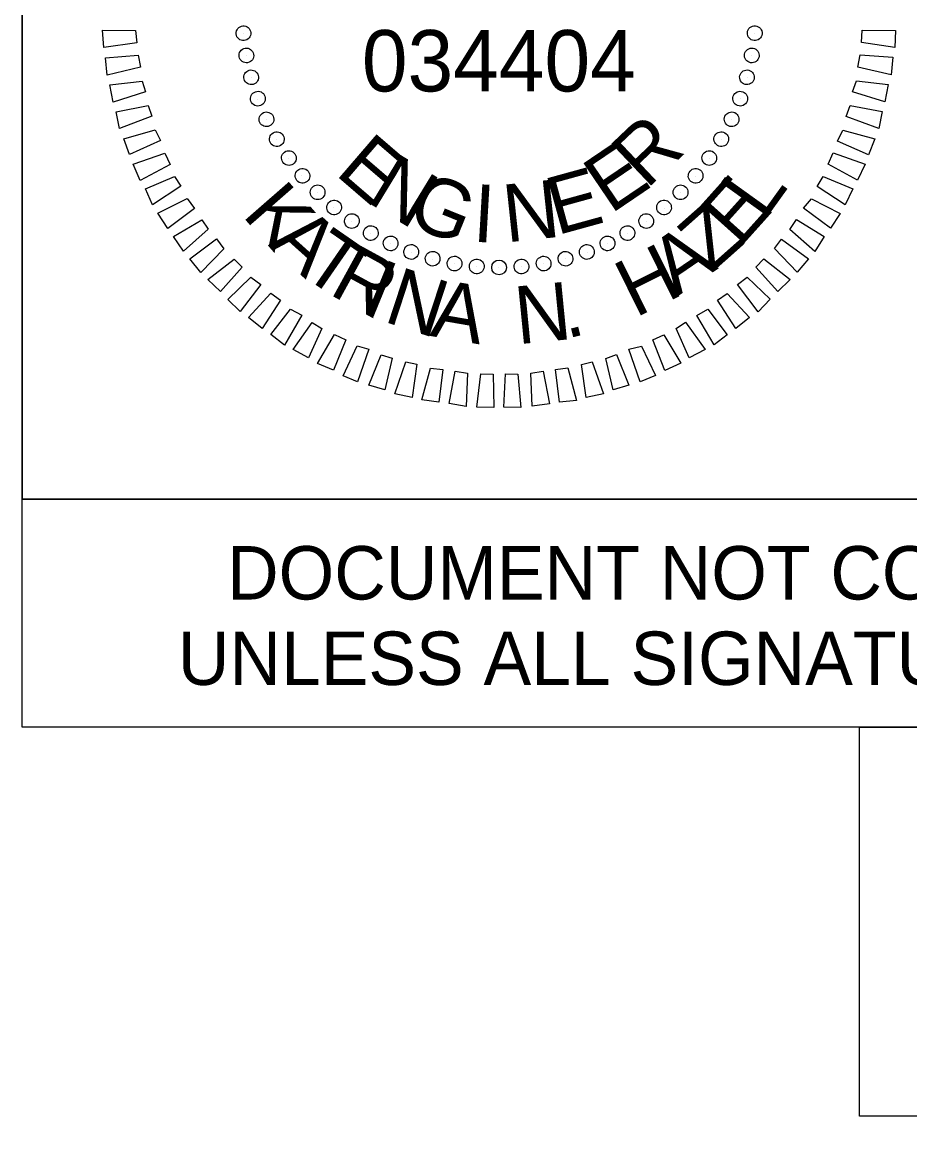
# Model space of a CAD drawing. Extents: x 2320980 to 2456309, y 595047 to 606177.
# Drawn here: x 2456002.1 to 2456020.37, y 597570.06 to 597592.89 of the extents above; entities that cross this region are included whole.
import ezdxf

# ---------------------------------------------------------------- set-up
doc = ezdxf.new("R2010")
doc.units = 0
for name, color, linetype in [('Scratch_Level_0', 7, 'Continuous'), ('Sheet Data Field CELL', 7, 'Continuous'), ('Sheet Plan CELL', 7, 'Continuous'), ('Sheet Sticker Exception Certification CELL', 7, 'Continuous')]:
    doc.layers.add(name, color=color, linetype=linetype)

msp = doc.modelspace()

# ---------------------------------------------------------------- linework, layer by layer
at = {"layer": 'Scratch_Level_0'}
msp.add_lwpolyline([(2456019.333, 597578.364), (2456042.107, 597578.366), (2456042.108, 597570.357), (2456019.334, 597570.354)], close=True, dxfattribs=at)
at = {"layer": 'Sheet Data Field CELL'}
for p, q in [((2456006.644, 597592.658), (2456006.644, 597592.658)), ((2456017.178, 597592.652), (2456017.178, 597592.652)), ((2456006.715, 597592.206), (2456006.715, 597592.206)), ((2456017.112, 597592.198), (2456017.112, 597592.198)), ((2456006.807, 597591.744), (2456006.807, 597591.744)), ((2456017.025, 597591.754), (2456017.025, 597591.754)), ((2456006.942, 597591.304), (2456006.942, 597591.304)), ((2456016.885, 597591.309), (2456016.885, 597591.309)), ((2456007.117, 597590.886), (2456007.117, 597590.886)), ((2456016.703, 597590.884), (2456016.703, 597590.884)), ((2456007.335, 597590.479), (2456007.335, 597590.479)), ((2456016.499, 597590.47), (2456016.499, 597590.47)), ((2456007.584, 597590.083), (2456007.584, 597590.083)), ((2456016.243, 597590.086), (2456016.243, 597590.086)), ((2456007.854, 597589.719), (2456007.854, 597589.719)), ((2456015.965, 597589.713), (2456015.965, 597589.713)), ((2456008.176, 597589.377), (2456008.176, 597589.377)), ((2456015.655, 597589.381), (2456015.655, 597589.381)), ((2456008.508, 597589.067), (2456008.508, 597589.067)), ((2456015.313, 597589.059), (2456015.313, 597589.059)), ((2456008.881, 597588.789), (2456008.881, 597588.789)), ((2456014.949, 597588.789), (2456014.949, 597588.789)), ((2456009.265, 597588.532), (2456009.265, 597588.532)), ((2456014.553, 597588.54), (2456014.553, 597588.54)), ((2456009.679, 597588.329), (2456009.679, 597588.329)), ((2456014.146, 597588.322), (2456014.146, 597588.322)), ((2456010.104, 597588.146), (2456010.104, 597588.146)), ((2456010.549, 597588.007), (2456010.549, 597588.007)), ((2456013.287, 597588.012), (2456013.287, 597588.012)), ((2456013.728, 597588.146), (2456013.728, 597588.146)), ((2456010.993, 597587.92), (2456010.993, 597587.92)), ((2456011.447, 597587.854), (2456011.447, 597587.854)), ((2456011.911, 597587.83), (2456011.911, 597587.83)), ((2456012.374, 597587.849), (2456012.374, 597587.849)), ((2456012.826, 597587.92), (2456012.826, 597587.92))]:
    msp.add_line(p, q, dxfattribs=at)
for points in [[(2456004.456, 597592.461), (2456003.774, 597592.365), (2456003.746, 597592.723), (2456004.431, 597592.714)], [(2456019.388, 597592.722), (2456020.073, 597592.713), (2456020.058, 597592.365), (2456019.372, 597592.469)], [(2456004.529, 597591.957), (2456003.847, 597591.798), (2456003.809, 597592.155), (2456004.482, 597592.209)], [(2456019.344, 597592.216), (2456020.02, 597592.164), (2456019.984, 597591.805), (2456019.296, 597591.962)], [(2456004.632, 597591.453), (2456003.972, 597591.242), (2456003.903, 597591.598), (2456004.565, 597591.673)], [(2456019.27, 597591.677), (2456019.924, 597591.604), (2456019.856, 597591.245), (2456019.189, 597591.454)], [(2456004.767, 597590.95), (2456004.098, 597590.696), (2456004.028, 597591.042), (2456004.69, 597591.17)], [(2456019.142, 597591.169), (2456019.797, 597591.044), (2456019.729, 597590.695), (2456019.061, 597590.947)], [(2456004.945, 597590.447), (2456004.307, 597590.162), (2456004.186, 597590.487), (2456004.835, 597590.667)], [(2456018.992, 597590.661), (2456019.649, 597590.483), (2456019.517, 597590.154), (2456018.88, 597590.438)], [(2456005.143, 597589.956), (2456004.527, 597589.629), (2456004.384, 597589.964), (2456005.033, 597590.186)], [(2456018.79, 597590.194), (2456019.447, 597589.963), (2456019.295, 597589.634), (2456018.689, 597589.961)], [(2456005.361, 597589.507), (2456004.778, 597589.128), (2456004.635, 597589.452), (2456005.231, 597589.705)], [(2456018.588, 597589.706), (2456019.193, 597589.453), (2456019.04, 597589.124), (2456018.465, 597589.504)], [(2456005.643, 597589.048), (2456005.092, 597588.638), (2456004.886, 597588.951), (2456005.492, 597589.256)], [(2456018.343, 597589.249), (2456018.938, 597588.943), (2456018.733, 597588.645), (2456018.178, 597589.056)], [(2456005.924, 597588.621), (2456005.416, 597588.17), (2456005.211, 597588.472), (2456005.795, 597588.819)], [(2456018.034, 597588.822), (2456018.609, 597588.474), (2456018.415, 597588.165), (2456017.901, 597588.62)], [(2456006.248, 597588.216), (2456005.771, 597587.734), (2456005.545, 597588.014), (2456006.096, 597588.424)], [(2456017.725, 597588.416), (2456018.28, 597588.015), (2456018.053, 597587.737), (2456017.581, 597588.224)], [(2456006.623, 597587.843), (2456006.179, 597587.341), (2456005.921, 597587.589), (2456006.462, 597588.009)], [(2456017.364, 597588.01), (2456017.909, 597587.587), (2456017.649, 597587.341), (2456017.198, 597587.838)], [(2456007.008, 597587.481), (2456006.586, 597586.926), (2456006.329, 597587.175), (2456006.805, 597587.636)], [(2456017.023, 597587.635), (2456017.494, 597587.18), (2456017.246, 597586.923), (2456016.825, 597587.484)], [(2456007.414, 597587.162), (2456007.035, 597586.576), (2456006.757, 597586.803), (2456007.212, 597587.306)], [(2456016.607, 597587.301), (2456017.069, 597586.804), (2456016.788, 597586.578), (2456016.41, 597587.161)], [(2456007.851, 597586.854), (2456007.493, 597586.236), (2456007.216, 597586.453), (2456007.617, 597586.976)], [(2456016.213, 597586.979), (2456016.612, 597586.448), (2456016.341, 597586.243), (2456015.983, 597586.848)], [(2456008.267, 597586.577), (2456007.993, 597585.971), (2456007.674, 597586.145), (2456008.065, 597586.699)], [(2456015.754, 597586.707), (2456016.154, 597586.145), (2456015.83, 597585.971), (2456015.556, 597586.577)], [(2456008.756, 597586.343), (2456008.503, 597585.717), (2456008.174, 597585.859), (2456008.522, 597586.455)], [(2456015.306, 597586.446), (2456015.653, 597585.863), (2456015.329, 597585.71), (2456015.076, 597586.348)], [(2456009.233, 597586.151), (2456009.002, 597585.483), (2456008.705, 597585.604), (2456008.989, 597586.22)], [(2456014.846, 597586.217), (2456015.131, 597585.611), (2456014.817, 597585.479), (2456014.584, 597586.149)], [(2456009.71, 597585.97), (2456009.564, 597585.314), (2456009.235, 597585.414), (2456009.488, 597586.039)], [(2456014.333, 597586.04), (2456014.586, 597585.412), (2456014.262, 597585.312), (2456014.113, 597585.962)], [(2456010.218, 597585.842), (2456010.125, 597585.155), (2456009.765, 597585.233), (2456009.996, 597585.89)], [(2456010.757, 597585.735), (2456010.674, 597585.06), (2456010.326, 597585.106), (2456010.504, 597585.762)], [(2456013.327, 597585.769), (2456013.507, 597585.098), (2456013.16, 597585.061), (2456013.074, 597585.733)], [(2456013.83, 597585.894), (2456014.063, 597585.235), (2456013.706, 597585.155), (2456013.61, 597585.838)], [(2456011.264, 597585.66), (2456011.234, 597584.975), (2456010.885, 597585.032), (2456011.01, 597585.697)], [(2456011.791, 597585.637), (2456011.803, 597584.953), (2456011.455, 597584.957), (2456011.538, 597585.643)], [(2456012.297, 597585.636), (2456012.361, 597584.952), (2456012.014, 597584.957), (2456012.044, 597585.642)], [(2456012.822, 597585.697), (2456012.95, 597585.026), (2456012.593, 597584.977), (2456012.57, 597585.661)]]:
    msp.add_lwpolyline(points, close=True, dxfattribs=at)
for centre, major_axis in [((2456006.651, 597592.658), (-0.151, -0.013)), ((2456017.176, 597592.658), (0.151, -0.013)), ((2456006.711, 597592.201), (-0.149, -0.026)), ((2456017.116, 597592.201), (0.149, -0.026)), ((2456006.81, 597591.751), (-0.146, -0.039)), ((2456017.016, 597591.751), (0.146, -0.039)), ((2456006.949, 597591.311), (-0.143, -0.052)), ((2456016.877, 597591.311), (0.143, -0.052)), ((2456007.125, 597590.886), (-0.137, -0.064)), ((2456016.701, 597590.886), (0.137, -0.064)), ((2456007.338, 597590.477), (-0.131, -0.076)), ((2456016.488, 597590.477), (0.131, -0.076)), ((2456007.586, 597590.088), (-0.124, -0.087)), ((2456016.241, 597590.088), (0.124, -0.087)), ((2456007.866, 597589.722), (-0.116, -0.097)), ((2456015.96, 597589.722), (0.116, -0.097)), ((2456008.178, 597589.383), (-0.107, -0.107)), ((2456015.649, 597589.383), (0.107, -0.107)), ((2456008.518, 597589.071), (-0.097, -0.116)), ((2456015.309, 597589.071), (0.097, -0.116)), ((2456008.883, 597588.791), (-0.087, -0.124)), ((2456014.943, 597588.791), (0.087, -0.124)), ((2456009.272, 597588.543), (-0.076, -0.131)), ((2456014.555, 597588.543), (0.076, -0.131)), ((2456009.681, 597588.33), (-0.064, -0.137)), ((2456014.146, 597588.33), (0.064, -0.137)), ((2456010.106, 597588.154), (-0.052, -0.143)), ((2456013.72, 597588.154), (0.052, -0.143)), ((2456010.546, 597588.015), (-0.039, -0.146)), ((2456010.996, 597587.916), (-0.026, -0.149)), ((2456011.453, 597587.855), (-0.013, -0.151)), ((2456012.374, 597587.855), (0.013, -0.151)), ((2456012.831, 597587.916), (0.026, -0.149)), ((2456013.281, 597588.015), (0.039, -0.146)), ((2456011.913, 597587.835), (0, -0.152))]:
    msp.add_ellipse(centre, major_axis=major_axis, ratio=0.999708, dxfattribs=at)
at = {"layer": 'Sheet Plan CELL'}
for points in [[(2455742.104, 597403.076), (2455742.099, 597613.071), (2456002.097, 597613.079), (2456002.099, 597583.066), (2456042.107, 597583.064), (2456042.107, 597403.076)], [(2456002.097, 597605.564), (2456022.107, 597605.564), (2456022.107, 597583.061), (2456002.099, 597583.066)]]:
    msp.add_lwpolyline(points, close=True, dxfattribs=at)
at = {"layer": 'Sheet Sticker Exception Certification CELL'}
for p, q in [((2456002.099, 597578.366), (2456002.099, 597583.066)), ((2456002.099, 597583.066), (2456042.107, 597583.066)), ((2456002.099, 597578.366), (2456002.099, 597583.066)), ((2456002.099, 597583.066), (2456042.107, 597583.066)), ((2456042.107, 597578.366), (2456002.099, 597578.366)), ((2456042.107, 597578.366), (2456002.099, 597578.366))]:
    msp.add_line(p, q, dxfattribs=at)

# ---------------------------------------------------------------- texts
at = {"layer": 'Sheet Data Field CELL'}
for s, height, rotation, p in [('034404', 1.2638, 0, (2456009.089, 597591.46)), ('R', 1.188, 43.4814, (2456014.948, 597589.432)), ('E', 1.188, 319.2769, (2456008.517, 597589.762)), ('E', 1.188, 34.1241, (2456014.209, 597588.924)), ('N', 1.188, 328.634, (2456009.159, 597589.204)), ('E', 1.188, 15.4118, (2456013.1, 597588.494)), ('G', 1.188, 337.9902, (2456009.967, 597588.744)), ('N', 1.188, 6.0564, (2456012.06, 597588.349)), ('E', 1.188, 48.1243, (2456016.869, 597588.232)), ('L', 1.188, 54.2991, (2456017.366, 597588.78)), ('K', 1.188, 311.168, (2456006.605, 597588.914)), ('I', 1.188, 356.7012, (2456011.354, 597588.368)), ('Z', 1.188, 41.5848, (2456016.281, 597587.714)), ('A', 1.188, 318.0722, (2456007.149, 597588.292)), ('T', 1.188, 325.3219, (2456007.797, 597587.713)), ('A', 1.188, 34.3351, (2456015.565, 597587.222)), ('R', 1.188, 331.3047, (2456008.384, 597587.301)), ('H', 1.188, 26.3751, (2456014.715, 597586.79)), ('I', 1.188, 337.7098, (2456009.055, 597586.929)), ('N', 1.188, 341.8307, (2456009.508, 597586.731)), ('A', 1.188, 350.2514, (2456010.47, 597586.429)), ('N', 1.188, 5.5954, (2456012.296, 597586.252)), ('.', 1.188, 14.016, (2456013.299, 597586.364))]:
    msp.add_text(s, height=height, rotation=rotation, dxfattribs=at).set_placement(p)
at = {"layer": 'Sheet Sticker Exception Certification CELL'}
for s, p in [('DOCUMENT NOT CONSIDERED FINAL', (2456006.313, 597580.997)), ('DOCUMENT NOT CONSIDERED FINAL', (2456006.313, 597580.997)), ('UNLESS ALL SIGNATURES COMPLETED', (2456005.299, 597579.237)), ('UNLESS ALL SIGNATURES COMPLETED', (2456005.299, 597579.237))]:
    msp.add_text(s, height=1.1, dxfattribs=at).set_placement(p)

doc.saveas('drawing.dxf')
